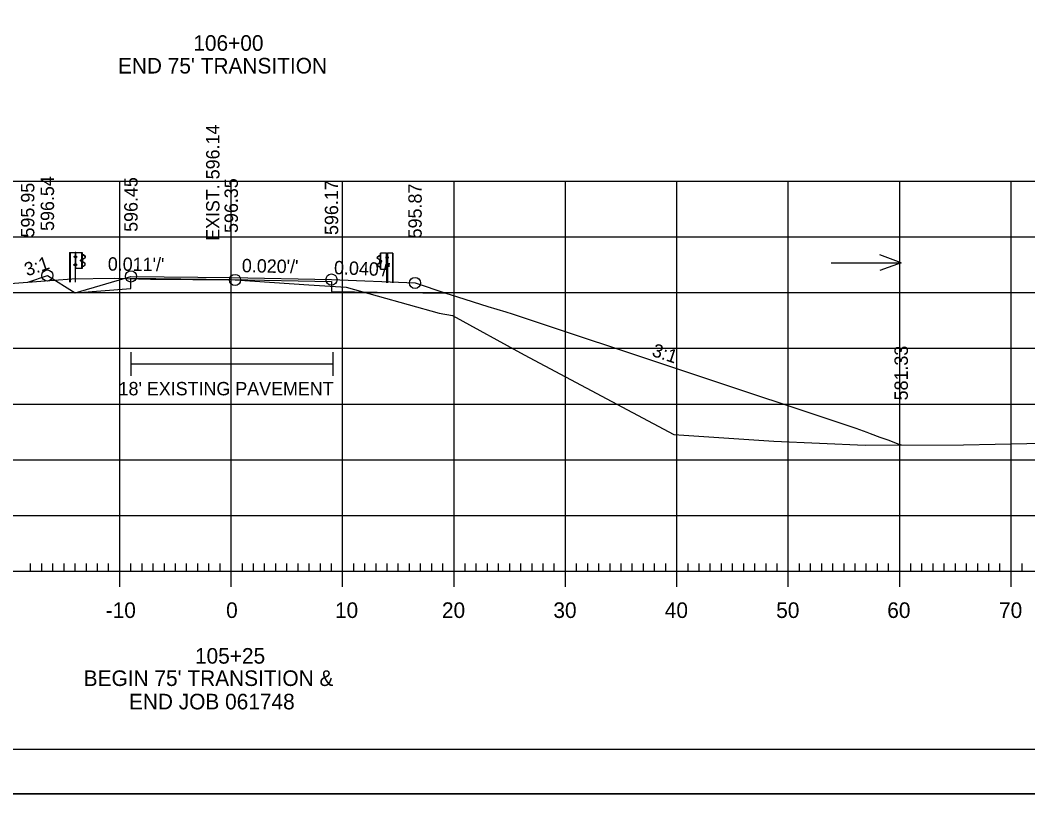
# Model space of a CAD drawing. Extents: x 961436 to 1372525, y 380079 to 2027791.
# Drawn here: x 1370614.9 to 1370705.3, y 380535.8 to 380605.2 of the extents above; entities that cross this region are included whole.
import ezdxf

# ---------------------------------------------------------------- set-up
doc = ezdxf.new("R2010")
doc.units = 0
for name, color, linetype in [('R_Alt Surface', 7, 'Continuous'), ('R_Axis', 7, 'Continuous'), ('R_Axis Annot', 7, 'Continuous'), ('R_Drive', 7, 'Continuous'), ('R_Exist Surface', 7, 'Continuous'), ('R_Fin Surface', 7, 'Continuous'), ('R_Fin Surface Annot', 7, 'Continuous'), ('R_Grid', 7, 'Continuous'), ('R_No Plot', 7, 'Continuous'), ('R_Proposed Road', 7, 'Continuous'), ('R_Water Annot', 7, 'Continuous'), ('R_Xsect Elev', 7, 'Continuous')]:
    doc.layers.add(name, color=color, linetype=linetype)

msp = doc.modelspace()

# ---------------------------------------------------------------- linework, layer by layer
at = {"layer": 'R_Alt Surface'}
msp.add_lwpolyline([(1370619.812, 380580.722), (1370624.812, 380581.103), (1370624.802, 380581.103), (1370624.812, 380582.019), (1370633.812, 380581.918), (1370642.812, 380581.738), (1370642.822, 380580.821), (1370642.812, 380580.822), (1370653.073, 380580.685)], dxfattribs=at)
at = {"layer": 'R_Axis'}
for p, q in [((1370623.812, 380554.335), (1370623.812, 380557.135)), ((1370633.812, 380554.335), (1370633.812, 380557.135)), ((1370643.812, 380554.335), (1370643.812, 380557.135)), ((1370653.812, 380554.335), (1370653.812, 380557.135)), ((1370663.812, 380554.335), (1370663.812, 380557.135)), ((1370673.812, 380554.335), (1370673.812, 380557.135)), ((1370683.812, 380554.335), (1370683.812, 380557.135)), ((1370693.812, 380554.335), (1370693.812, 380557.135)), ((1370703.812, 380554.335), (1370703.812, 380557.135)), ((1370615.812, 380555.735), (1370615.812, 380556.435)), ((1370616.812, 380555.735), (1370616.812, 380556.435)), ((1370617.812, 380555.735), (1370617.812, 380556.435)), ((1370618.812, 380555.735), (1370618.812, 380556.435)), ((1370619.812, 380555.735), (1370619.812, 380556.435)), ((1370620.812, 380555.735), (1370620.812, 380556.435)), ((1370621.812, 380555.735), (1370621.812, 380556.435)), ((1370622.812, 380555.735), (1370622.812, 380556.435)), ((1370624.812, 380555.735), (1370624.812, 380556.435)), ((1370625.812, 380555.735), (1370625.812, 380556.435)), ((1370626.812, 380555.735), (1370626.812, 380556.435)), ((1370627.812, 380555.735), (1370627.812, 380556.435)), ((1370628.812, 380555.735), (1370628.812, 380556.435)), ((1370629.812, 380555.735), (1370629.812, 380556.435)), ((1370630.812, 380555.735), (1370630.812, 380556.435)), ((1370631.812, 380555.735), (1370631.812, 380556.435)), ((1370632.812, 380555.735), (1370632.812, 380556.435)), ((1370634.812, 380555.735), (1370634.812, 380556.435)), ((1370635.812, 380555.735), (1370635.812, 380556.435)), ((1370636.812, 380555.735), (1370636.812, 380556.435)), ((1370637.812, 380555.735), (1370637.812, 380556.435)), ((1370638.812, 380555.735), (1370638.812, 380556.435)), ((1370639.812, 380555.735), (1370639.812, 380556.435)), ((1370640.812, 380555.735), (1370640.812, 380556.435)), ((1370641.812, 380555.735), (1370641.812, 380556.435)), ((1370642.812, 380555.735), (1370642.812, 380556.435)), ((1370644.812, 380555.735), (1370644.812, 380556.435)), ((1370645.812, 380555.735), (1370645.812, 380556.435)), ((1370646.812, 380555.735), (1370646.812, 380556.435)), ((1370647.812, 380555.735), (1370647.812, 380556.435)), ((1370648.812, 380555.735), (1370648.812, 380556.435)), ((1370649.812, 380555.735), (1370649.812, 380556.435)), ((1370650.812, 380555.735), (1370650.812, 380556.435)), ((1370651.812, 380555.735), (1370651.812, 380556.435)), ((1370652.812, 380555.735), (1370652.812, 380556.435)), ((1370654.812, 380555.735), (1370654.812, 380556.435)), ((1370655.812, 380555.735), (1370655.812, 380556.435)), ((1370656.812, 380555.735), (1370656.812, 380556.435)), ((1370657.812, 380555.735), (1370657.812, 380556.435)), ((1370658.812, 380555.735), (1370658.812, 380556.435)), ((1370659.812, 380555.735), (1370659.812, 380556.435)), ((1370660.812, 380555.735), (1370660.812, 380556.435)), ((1370661.812, 380555.735), (1370661.812, 380556.435)), ((1370662.812, 380555.735), (1370662.812, 380556.435)), ((1370664.812, 380555.735), (1370664.812, 380556.435)), ((1370665.812, 380555.735), (1370665.812, 380556.435)), ((1370666.812, 380555.735), (1370666.812, 380556.435)), ((1370667.812, 380555.735), (1370667.812, 380556.435)), ((1370668.812, 380555.735), (1370668.812, 380556.435)), ((1370669.812, 380555.735), (1370669.812, 380556.435)), ((1370670.812, 380555.735), (1370670.812, 380556.435)), ((1370671.812, 380555.735), (1370671.812, 380556.435)), ((1370672.812, 380555.735), (1370672.812, 380556.435)), ((1370674.812, 380555.735), (1370674.812, 380556.435)), ((1370675.812, 380555.735), (1370675.812, 380556.435)), ((1370676.812, 380555.735), (1370676.812, 380556.435)), ((1370677.812, 380555.735), (1370677.812, 380556.435)), ((1370678.812, 380555.735), (1370678.812, 380556.435)), ((1370679.812, 380555.735), (1370679.812, 380556.435)), ((1370680.812, 380555.735), (1370680.812, 380556.435)), ((1370681.812, 380555.735), (1370681.812, 380556.435)), ((1370682.812, 380555.735), (1370682.812, 380556.435)), ((1370684.812, 380555.735), (1370684.812, 380556.435)), ((1370685.812, 380555.735), (1370685.812, 380556.435)), ((1370686.812, 380555.735), (1370686.812, 380556.435)), ((1370687.812, 380555.735), (1370687.812, 380556.435)), ((1370688.812, 380555.735), (1370688.812, 380556.435)), ((1370689.812, 380555.735), (1370689.812, 380556.435)), ((1370690.812, 380555.735), (1370690.812, 380556.435)), ((1370691.812, 380555.735), (1370691.812, 380556.435)), ((1370692.812, 380555.735), (1370692.812, 380556.435)), ((1370694.812, 380555.735), (1370694.812, 380556.435)), ((1370695.812, 380555.735), (1370695.812, 380556.435)), ((1370696.812, 380555.735), (1370696.812, 380556.435)), ((1370697.812, 380555.735), (1370697.812, 380556.435)), ((1370698.812, 380555.735), (1370698.812, 380556.435)), ((1370699.812, 380555.735), (1370699.812, 380556.435)), ((1370700.812, 380555.735), (1370700.812, 380556.435)), ((1370701.812, 380555.735), (1370701.812, 380556.435)), ((1370702.812, 380555.735), (1370702.812, 380556.435)), ((1370704.812, 380555.735), (1370704.812, 380556.435)), ((1370493.812, 380555.735), (1370773.812, 380555.735))]:
    msp.add_line(p, q, dxfattribs=at)
at = {"layer": 'R_Drive'}
for p, q in [((1370624.798, 380575.401), (1370624.798, 380573.265)), ((1370642.926, 380575.401), (1370642.926, 380573.265)), ((1370624.798, 380574.333), (1370642.926, 380574.333))]:
    msp.add_line(p, q, dxfattribs=at)
at = {"layer": 'R_Exist Surface'}
msp.add_lwpolyline([(1370613.156, 380581.501), (1370619.515, 380581.981), (1370623.319, 380582.018), (1370626.562, 380581.934), (1370634.16, 380581.874), (1370640.767, 380581.446), (1370644.144, 380581.216), (1370652.483, 380578.892), (1370653.668, 380578.691), (1370660.106, 380575.137), (1370673.538, 380568.01), (1370682.504, 380567.41), (1370690.703, 380567.05), (1370699.543, 380567.08), (1370708.057, 380567.263)], dxfattribs=at)
at = {"layer": 'R_Fin Surface'}
msp.add_lwpolyline([(1370615.545, 380581.681), (1370617.312, 380582.27), (1370619.812, 380580.722), (1370624.812, 380582.186), (1370633.812, 380582.085), (1370642.812, 380581.905), (1370650.312, 380581.605), (1370653.073, 380580.685), (1370654.114, 380580.357), (1370656.85, 380579.502), (1370658.454, 380579.006), (1370659.032, 380578.828), (1370689.882, 380568.575), (1370690.858, 380568.203), (1370691.17, 380568.085), (1370692.022, 380567.767), (1370692.838, 380567.49), (1370693.641, 380567.177), (1370693.943, 380567.061)], dxfattribs=at)
at = {"layer": 'R_Grid'}
for p, q in [((1370493.812, 380590.735), (1370773.812, 380590.735)), ((1370623.812, 380555.735), (1370623.812, 380590.735)), ((1370633.812, 380555.735), (1370633.812, 380590.735)), ((1370643.812, 380555.735), (1370643.812, 380590.735)), ((1370653.812, 380555.735), (1370653.812, 380590.735)), ((1370663.812, 380555.735), (1370663.812, 380590.735)), ((1370673.812, 380555.735), (1370673.812, 380590.735)), ((1370683.812, 380555.735), (1370683.812, 380590.735)), ((1370693.812, 380555.735), (1370693.812, 380590.735)), ((1370703.812, 380555.735), (1370703.812, 380590.735)), ((1370493.812, 380585.735), (1370773.812, 380585.735)), ((1370493.812, 380580.735), (1370773.812, 380580.735)), ((1370493.812, 380575.735), (1370773.812, 380575.735)), ((1370493.812, 380570.735), (1370773.812, 380570.735)), ((1370493.812, 380565.735), (1370773.812, 380565.735)), ((1370493.812, 380560.735), (1370773.812, 380560.735)), ((1370493.812, 380555.735), (1370773.812, 380555.735))]:
    msp.add_line(p, q, dxfattribs=at)
at = {"layer": 'R_No Plot'}
for p, q in [((1370791.992, 380539.735), (1370475.812, 380539.735)), ((1370463.411, 380535.756), (1370796.745, 380535.756))]:
    msp.add_line(p, q, dxfattribs=at)
for points in [[(1370463.405, 380749.09), (1370796.745, 380749.09), (1370796.745, 380535.752), (1370463.405, 380535.752)], [(1370709.732, 380745.195), (1370729.352, 380745.195), (1370729.352, 380735.315), (1370745.464, 380735.315), (1370768.664, 380735.315), (1370768.784, 380707.158), (1370791.992, 380707.158), (1370791.992, 380539.735), (1370475.812, 380539.735), (1370475.812, 380745.195)]]:
    msp.add_lwpolyline(points, close=True, dxfattribs=at)
for centre in [(1370617.312, 380582.27), (1370624.812, 380582.186), (1370634.16, 380581.874), (1370642.812, 380581.905), (1370650.312, 380581.605)]:
    msp.add_circle(centre, 0.5, dxfattribs=at)
at = {"layer": 'R_Proposed Road'}
for p, q in [((1370619.313, 380584.338), (1370619.313, 380581.668)), ((1370619.344, 380584.338), (1370619.344, 380581.668)), ((1370619.87, 380584.34), (1370619.797, 380584.337)), ((1370619.834, 380581.668), (1370619.834, 380584.34)), ((1370619.87, 380584.34), (1370619.864, 380584.34)), ((1370620.4, 380582.888), (1370620.4, 380584.332)), ((1370620.553, 380584.111), (1370620.434, 380584.175)), ((1370620.539, 380584.094), (1370620.44, 380584.147)), ((1370647.225, 380582.825), (1370647.225, 380584.269)), ((1370647.755, 380584.277), (1370647.761, 380584.277)), ((1370647.755, 380584.277), (1370647.828, 380584.274)), ((1370647.791, 380581.605), (1370647.791, 380584.277)), ((1370648.28, 380584.275), (1370648.28, 380581.605)), ((1370648.312, 380584.275), (1370648.312, 380581.605)), ((1370619.727, 380583.17), (1370619.727, 380583.271)), ((1370619.785, 380583.254), (1370619.732, 380583.254)), ((1370619.785, 380583.287), (1370619.733, 380583.287)), ((1370619.737, 380583.903), (1370619.737, 380584.003)), ((1370619.796, 380583.886), (1370619.743, 380583.886)), ((1370619.796, 380583.987), (1370619.744, 380583.987)), ((1370619.796, 380583.919), (1370619.744, 380583.919)), ((1370619.796, 380584.019), (1370619.745, 380584.019)), ((1370619.796, 380583.919), (1370619.75, 380583.919)), ((1370619.785, 380583.155), (1370619.785, 380583.287)), ((1370619.796, 380583.886), (1370619.796, 380584.019)), ((1370619.928, 380583.946), (1370619.869, 380583.946)), ((1370619.928, 380583.22), (1370619.869, 380583.22)), ((1370619.876, 380583.881), (1370619.929, 380583.881)), ((1370619.877, 380584.013), (1370619.929, 380584.013)), ((1370619.929, 380583.287), (1370619.877, 380583.287)), ((1370619.929, 380584.013), (1370619.929, 380583.881)), ((1370619.929, 380583.155), (1370619.929, 380583.287)), ((1370620.327, 380583.561), (1370620.327, 380583.662)), ((1370620.386, 380583.545), (1370620.333, 380583.545)), ((1370620.386, 380583.645), (1370620.334, 380583.645)), ((1370620.386, 380583.577), (1370620.334, 380583.577)), ((1370620.386, 380583.678), (1370620.335, 380583.678)), ((1370620.386, 380583.577), (1370620.34, 380583.577)), ((1370620.386, 380583.545), (1370620.386, 380583.678)), ((1370620.441, 380583.546), (1370620.443, 380583.685)), ((1370620.467, 380583.545), (1370620.469, 380583.685)), ((1370620.65, 380583.364), (1370620.486, 380583.467)), ((1370620.491, 380583.759), (1370620.674, 380583.87)), ((1370620.663, 380583.385), (1370620.499, 380583.488)), ((1370620.505, 380583.736), (1370620.687, 380583.848)), ((1370620.677, 380583.984), (1370620.539, 380584.094)), ((1370620.544, 380583.118), (1370620.678, 380583.234)), ((1370620.691, 380584.001), (1370620.553, 380584.111)), ((1370620.559, 380583.101), (1370620.693, 380583.217)), ((1370646.934, 380583.937), (1370647.072, 380584.048)), ((1370647.12, 380583.673), (1370646.938, 380583.784)), ((1370646.948, 380583.92), (1370647.086, 380584.031)), ((1370647.134, 380583.695), (1370646.951, 380583.807)), ((1370646.962, 380583.322), (1370647.125, 380583.425)), ((1370646.975, 380583.3), (1370647.139, 380583.403)), ((1370647.072, 380584.048), (1370647.191, 380584.111)), ((1370647.086, 380584.031), (1370647.185, 380584.084)), ((1370647.158, 380583.482), (1370647.156, 380583.622)), ((1370647.184, 380583.483), (1370647.182, 380583.622)), ((1370647.239, 380583.482), (1370647.239, 380583.615)), ((1370647.239, 380583.615), (1370647.29, 380583.615)), ((1370647.239, 380583.582), (1370647.291, 380583.582)), ((1370647.239, 380583.514), (1370647.285, 380583.514)), ((1370647.239, 380583.514), (1370647.291, 380583.514)), ((1370647.239, 380583.482), (1370647.292, 380583.482)), ((1370647.297, 380583.498), (1370647.297, 380583.599)), ((1370647.748, 380583.95), (1370647.695, 380583.95)), ((1370647.695, 380583.95), (1370647.695, 380583.817)), ((1370647.749, 380583.817), (1370647.695, 380583.817)), ((1370647.695, 380583.091), (1370647.695, 380583.224)), ((1370647.695, 380583.224), (1370647.748, 380583.224)), ((1370647.697, 380583.883), (1370647.756, 380583.883)), ((1370647.829, 380583.823), (1370647.829, 380583.955)), ((1370647.829, 380583.955), (1370647.88, 380583.955)), ((1370647.829, 380583.924), (1370647.881, 380583.924)), ((1370647.829, 380583.856), (1370647.875, 380583.856)), ((1370647.829, 380583.856), (1370647.881, 380583.856)), ((1370647.829, 380583.823), (1370647.882, 380583.823)), ((1370647.84, 380583.091), (1370647.84, 380583.224)), ((1370647.84, 380583.224), (1370647.892, 380583.224)), ((1370647.888, 380583.84), (1370647.888, 380583.939)), ((1370619.785, 380583.186), (1370619.732, 380583.186)), ((1370619.785, 380583.155), (1370619.732, 380583.155)), ((1370619.785, 380583.186), (1370619.739, 380583.186)), ((1370619.869, 380582.888), (1370619.833, 380582.888)), ((1370619.929, 380583.155), (1370619.876, 380583.155)), ((1370620.429, 380583.06), (1370620.544, 380583.118)), ((1370620.438, 380583.04), (1370620.559, 380583.101)), ((1370647.066, 380583.038), (1370646.932, 380583.154)), ((1370647.081, 380583.055), (1370646.947, 380583.171)), ((1370647.187, 380582.977), (1370647.066, 380583.038)), ((1370647.195, 380582.997), (1370647.081, 380583.055)), ((1370647.695, 380583.091), (1370647.749, 380583.091)), ((1370647.697, 380583.157), (1370647.756, 380583.157)), ((1370647.756, 380582.825), (1370647.792, 380582.825)), ((1370647.84, 380583.191), (1370647.893, 380583.191)), ((1370647.84, 380583.123), (1370647.886, 380583.123)), ((1370647.84, 380583.123), (1370647.893, 380583.123)), ((1370647.84, 380583.091), (1370647.893, 380583.091)), ((1370647.898, 380583.107), (1370647.898, 380583.208))]:
    msp.add_line(p, q, dxfattribs=at)
for points in [[(1370619.313, 380584.338), (1370619.797, 380584.337), (1370619.795, 380581.668)], [(1370648.312, 380584.275), (1370647.828, 380584.274), (1370647.83, 380581.605)]]:
    msp.add_lwpolyline(points, dxfattribs=at)
for points in [[(1370620.427, 380584.339), (1370620.426, 380582.888), (1370619.869, 380582.888), (1370619.87, 380584.34)], [(1370647.198, 380584.276), (1370647.199, 380582.825), (1370647.756, 380582.825), (1370647.755, 380584.277)], [(1370619.723, 380583.254), (1370619.723, 380583.187), (1370619.697, 380583.187), (1370619.697, 380583.254)], [(1370619.735, 380583.986), (1370619.735, 380583.92), (1370619.709, 380583.92), (1370619.709, 380583.986)], [(1370619.783, 380583.308), (1370619.783, 380583.13), (1370619.794, 380583.13), (1370619.794, 380583.308)], [(1370619.795, 380584.04), (1370619.795, 380583.862), (1370619.805, 380583.862), (1370619.805, 380584.04)], [(1370619.928, 380584.013), (1370619.928, 380583.881), (1370619.87, 380583.881), (1370619.87, 380584.013)], [(1370619.928, 380583.287), (1370619.928, 380583.155), (1370619.87, 380583.155), (1370619.87, 380583.287)], [(1370620.325, 380583.645), (1370620.325, 380583.578), (1370620.299, 380583.578), (1370620.299, 380583.645)], [(1370620.385, 380583.699), (1370620.385, 380583.521), (1370620.395, 380583.521), (1370620.395, 380583.699)], [(1370647.24, 380583.636), (1370647.24, 380583.458), (1370647.229, 380583.458), (1370647.229, 380583.636)], [(1370647.3, 380583.582), (1370647.3, 380583.515), (1370647.326, 380583.515), (1370647.326, 380583.582)], [(1370647.697, 380583.95), (1370647.697, 380583.817), (1370647.755, 380583.817), (1370647.755, 380583.95)], [(1370647.697, 380583.224), (1370647.697, 380583.091), (1370647.755, 380583.091), (1370647.755, 380583.224)], [(1370647.83, 380583.977), (1370647.83, 380583.798), (1370647.82, 380583.798), (1370647.82, 380583.977)], [(1370647.842, 380583.245), (1370647.842, 380583.067), (1370647.831, 380583.067), (1370647.831, 380583.245)], [(1370647.89, 380583.922), (1370647.89, 380583.857), (1370647.916, 380583.857), (1370647.916, 380583.922)], [(1370647.901, 380583.191), (1370647.901, 380583.124), (1370647.928, 380583.124), (1370647.928, 380583.191)]]:
    msp.add_lwpolyline(points, close=True, dxfattribs=at)
for centre, radius, start, end in [((1370619.749, 380583.27), 0.0234, 134.57445, 222.22441), ((1370619.824, 380583.221), 0.0979, 159.74227, 200.25773), ((1370619.761, 380584.002), 0.0234, 134.57445, 222.22441), ((1370619.835, 380583.952), 0.0979, 159.74227, 200.25773), ((1370619.764, 380583.902), 0.0265, 140.93341, 216.62337), ((1370620.351, 380583.661), 0.0234, 134.57445, 222.22441), ((1370620.426, 380583.611), 0.0979, 159.74227, 200.25773), ((1370620.354, 380583.561), 0.0265, 140.93341, 216.62337), ((1370620.515, 380583.535), 0.0747, 171.78044, 246.85364), ((1370620.534, 380583.678), 0.0918, 118.10599, 175.04439), ((1370620.461, 380583.606), 0.0481, 282.95537, 86.06973), ((1370620.515, 380583.535), 0.049, 171.78044, 246.85364), ((1370620.534, 380583.678), 0.066, 118.10599, 175.04439), ((1370620.603, 380583.286), 0.0907, 325.21842, 59.11995), ((1370620.603, 380583.286), 0.116, 325.21843, 59.11995), ((1370620.642, 380583.928), 0.0658, 299.24991, 57.97825), ((1370620.642, 380583.928), 0.0909, 299.24991, 57.97825), ((1370646.983, 380583.864), 0.0909, 122.02175, 240.75009), ((1370647.022, 380583.223), 0.116, 120.88005, 214.78158), ((1370646.983, 380583.864), 0.0658, 122.02175, 240.75009), ((1370647.022, 380583.223), 0.0907, 120.88005, 214.78158), ((1370647.164, 380583.543), 0.0481, 93.93027, 257.04463), ((1370647.091, 380583.614), 0.066, 4.95561, 61.89401), ((1370647.11, 380583.472), 0.049, 293.14636, 8.21956), ((1370647.091, 380583.614), 0.0918, 4.95561, 61.89401), ((1370647.11, 380583.472), 0.0747, 293.14636, 8.21956), ((1370647.274, 380583.598), 0.0234, 317.77559, 45.42555), ((1370647.199, 380583.548), 0.0979, 339.74227, 20.25773), ((1370647.27, 380583.497), 0.0265, 323.37663, 39.06659), ((1370647.864, 380583.939), 0.0234, 317.77559, 45.42555), ((1370647.789, 380583.889), 0.0979, 339.74227, 20.25773), ((1370647.861, 380583.839), 0.0265, 323.37663, 39.06659), ((1370647.875, 380583.207), 0.0234, 317.77559, 45.42555), ((1370619.753, 380583.17), 0.0265, 140.93341, 216.62337), ((1370647.801, 380583.157), 0.0979, 339.74227, 20.25773), ((1370647.872, 380583.107), 0.0265, 323.37663, 39.06659)]:
    msp.add_arc(centre, radius, start, end, dxfattribs=at)
at = {"layer": 'R_Water Annot'}
for p, q in [((1370693.954, 380583.418), (1370692.03, 380584.118)), ((1370687.669, 380583.418), (1370693.954, 380583.418)), ((1370693.954, 380583.418), (1370692.03, 380582.717))]:
    msp.add_line(p, q, dxfattribs=at)

# ---------------------------------------------------------------- texts
at = {"layer": 'R_Axis Annot'}
for s, p in [('106+00', (1370630.411, 380602.435)), ("END 75' TRANSITION", (1370623.643, 380600.398)), ('-10', (1370622.55, 380551.535)), ('0', (1370633.355, 380551.535)), ('10', (1370643.123, 380551.535)), ('20', (1370652.726, 380551.535)), ('30', (1370662.726, 380551.535)), ('40', (1370672.726, 380551.535)), ('50', (1370682.726, 380551.535)), ('60', (1370692.693, 380551.535)), ('70', (1370702.726, 380551.535)), ('105+25', (1370630.56, 380547.435)), ("BEGIN 75' TRANSITION & ", (1370620.573, 380545.432)), ('END JOB 061748', (1370624.63, 380543.332))]:
    msp.add_text(s, height=1.4, dxfattribs=at).set_placement(p)
at = {"layer": 'R_Fin Surface Annot'}
for s, rotation, p in [('595.95', 90, (1370616.145, 380585.681)), ('596.54', 90, (1370617.912, 380586.27)), ('596.45', 90, (1370625.412, 380586.186)), ('596.35', 90, (1370634.412, 380586.085)), ('596.17', 90, (1370643.412, 380585.905)), ('595.87', 90, (1370650.912, 380585.605)), ('3:1', 18.43493, (1370615.482, 380582.187)), ("0.011'/'", 359.35614, (1370622.733, 380582.709)), ("0.020'/'", 358.85424, (1370634.761, 380582.566)), ("0.040'/'", 357.70939, (1370643.023, 380582.397)), ('3:1', 341.56507, (1370671.497, 380575.07)), ('581.33', 90, (1370694.543, 380571.061))]:
    msp.add_text(s, height=1.2, rotation=rotation, dxfattribs=at).set_placement(p)
msp.add_text("18' EXISTING PAVEMENT", height=1.2, dxfattribs=at).set_placement((1370623.707, 380571.515))
at = {"layer": 'R_Xsect Elev'}
msp.add_text('EXIST. 596.14', height=1.2, rotation=90, dxfattribs=at).set_placement((1370632.76, 380585.374))

doc.saveas('drawing.dxf')
